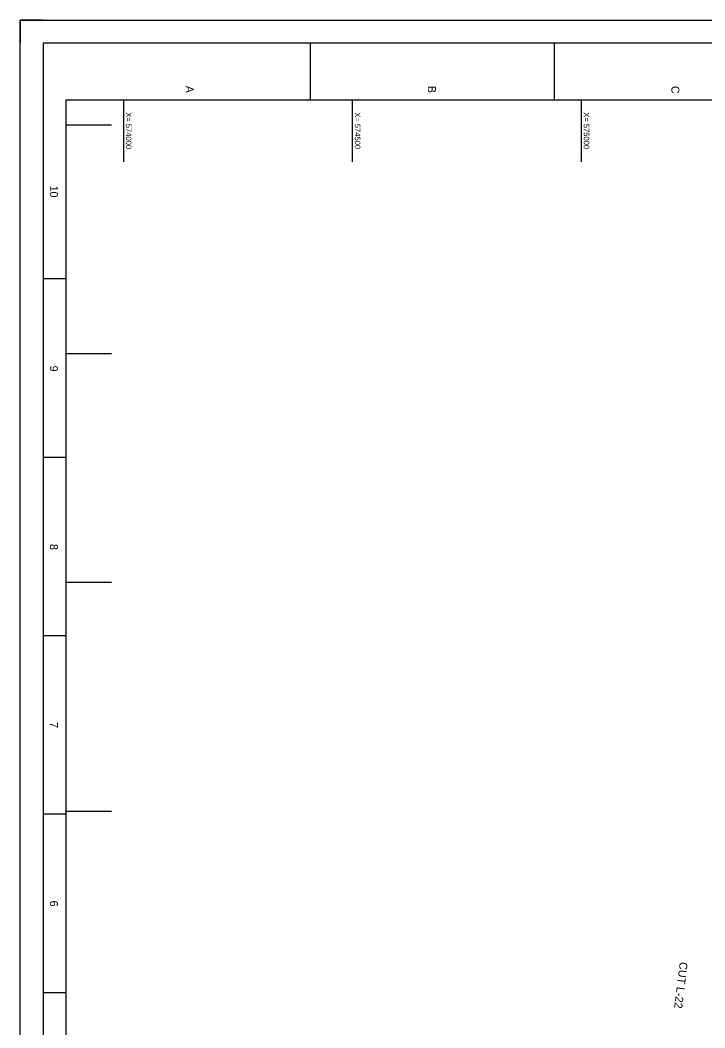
# Model space of a CAD drawing. Extents: x 573774 to 577174, y 877329 to 881729.
# Drawn here: x 573774 to 575269, y 879526 to 881729 of the extents above; entities that cross this region are included whole.
import ezdxf

# ---------------------------------------------------------------- set-up
doc = ezdxf.new("R2010")
doc.units = 0
for name, color, linetype in [('G-ANNO-NPLT', 7, 'Continuous'), ('G-ANNO-TTLB', 7, 'Continuous'), ('V-CHAN-CNTR-IDEN', 7, 'Continuous'), ('V-TOPO-COOR-STAT', 7, 'Continuous')]:
    doc.layers.add(name, color=color, linetype=linetype)

msp = doc.modelspace()

# ---------------------------------------------------------------- linework, layer by layer
at = {"layer": 'G-ANNO-NPLT'}
msp.add_lwpolyline([(577173.7, 881728.7), (577173.7, 877328.7), (573773.7, 877328.7), (573773.7, 881728.7)], close=True, dxfattribs=at)
msp.add_lwpolyline([(573823.7, 881728.7), (573773.7, 881728.7), (573773.7, 881678.7)], dxfattribs=at)
at = {"layer": 'G-ANNO-TTLB'}
for p, q in [((574407, 881678.7), (574407, 881553.7)), ((574940.3, 881678.7), (574940.3, 881553.7)), ((573823.7, 881163.7), (573873.7, 881163.7)), ((573823.7, 880773.7), (573873.7, 880773.7)), ((573823.7, 880383.7), (573873.7, 880383.7)), ((573823.7, 879993.7), (573873.7, 879993.7)), ((573823.7, 879603.7), (573873.7, 879603.7))]:
    msp.add_line(p, q, dxfattribs=at)
for points in [[(573823.7, 881678.7), (573823.7, 877378.7), (577123.7, 877378.7), (577123.7, 881678.7)], [(577073.7, 877428.7), (577073.7, 881553.7), (573873.7, 881553.7), (573873.7, 877428.7)]]:
    msp.add_lwpolyline(points, close=True, dxfattribs=at)
at = {"layer": 'V-TOPO-COOR-STAT'}
for p, q in [((574000, 881418.7), (574000, 881553.7)), ((574500, 881418.7), (574500, 881553.7)), ((575000, 881418.7), (575000, 881553.7)), ((573873.7, 881500), (573973.5, 881500)), ((573873.7, 881000), (573973.5, 881000)), ((573873.7, 880500), (573973.5, 880500)), ((573871.8, 880000), (573973.5, 880000))]:
    msp.add_line(p, q, dxfattribs=at)

# ---------------------------------------------------------------- texts
at = {"layer": 'G-ANNO-TTLB'}
for s, p in [('A', (574134.9, 881585.3)), ('B', (574664.4, 881585.2)), ('C', (575196.2, 881585)), ('10', (573838.7, 881367.1)), ('9', (573838.7, 880973.6)), ('8', (573838.7, 880583.8)), ('7', (573838.7, 880194.4)), ('6', (573838.7, 879804.4))]:
    msp.add_text(s, height=17.5, rotation=270, dxfattribs=at).set_placement(p)
at = {"layer": 'V-CHAN-CNTR-IDEN'}
msp.add_text('CUT L-22', height=17.52, rotation=262.9998, dxfattribs=at).set_placement((575214.6, 879670.7))
at = {"layer": 'V-TOPO-COOR-STAT'}
for s, p in [('X= 574000', (574004.8, 881527.5)), ('X= 574500', (574504.8, 881527.5)), ('X= 575000', (575004.8, 881527.5))]:
    msp.add_text(s, height=12, rotation=270, dxfattribs=at).set_placement(p)

doc.saveas('drawing.dxf')
